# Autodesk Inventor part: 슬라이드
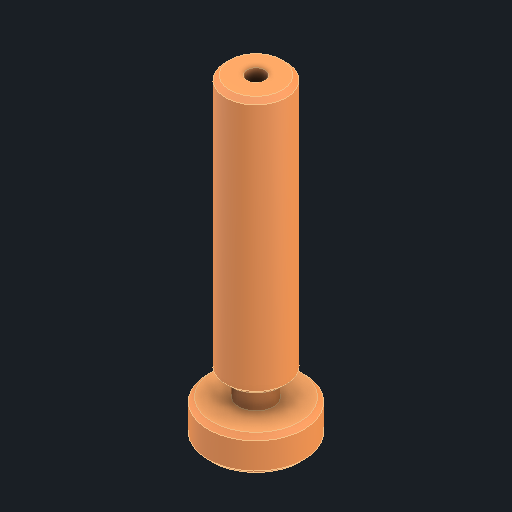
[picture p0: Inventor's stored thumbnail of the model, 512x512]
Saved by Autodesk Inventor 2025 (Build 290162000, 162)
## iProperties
Created: 2025-08
Part Number: 슬라이드
Material: 강철, 연강
Document SubType Name: Modeling
Designer: infra023
Density: 7.86 g/cm^3
Appearance: 기본값
Author: jhkim
Sending System: Autodesk Inventor 2026
Preprocessor: ST-DEVELOPER v20.1
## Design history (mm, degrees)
feature "솔리드1"
node "솔리드2"
